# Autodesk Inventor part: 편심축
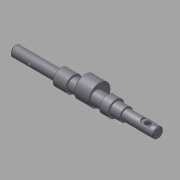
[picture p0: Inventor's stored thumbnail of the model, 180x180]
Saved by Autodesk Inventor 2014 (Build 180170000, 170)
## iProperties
Company: 한국ATC센터
Created: 2015-12
Part Number: 편심축
Document SubType Name: Modeling
Designer: mdu
Density: 7.86 g/cm^3
Mass: 248.518 g
Surface Area: 94.9944 cm^2
Volume: 31.6181 cm^3
Material: 강철, 연강
Appearance: 강철
Author: mdu
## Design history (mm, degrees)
sketch "스케치1"
  geometry: L1 (-84.5, 0)-(84.5, 0); L2 (-84.5, 0)-(-84.5, 6); L3 (-84.5, 6)-(-30.5, 6); L4 (-30.5, 6)-(-30.5, 9.5); L5 (-30.5, 9.5)-(-15.5, 9.5); L6 (-15.5, 9.5)-(-15.5, 7.5); L7 (-15.5, 7.5)-(46.5, 7.5); L8 (84.5, 6)-(84.5, 0); L9 (34.5, 7.5)-(34.5, 9.5); L10 (34.5, 9.5)-(24.5, 9.5); L11 (24.5, 9.5)-(24.5, 7.5); L12 (46.5, 7.5)-(46.5, 6); L13 (46.5, 6)-(84.5, 6); 2 further points
  constraints: 26 end point, 6 parallel, 6 perpendicular, 2 point on line, 1 coincident, 1 horizontal, 1 midpoint
  dimensions: "d1" = 12 diameter of L3 L1; "d2" = 15 diameter of L7 L1; "d4" = 15 distance of L4.end L5.end; "d5" = 19 diameter of L5 L1; "d24" = 10 distance of L9.end L10.end; "d25" = 19 diameter of L10 L1; "d27" = 40 distance between parallel lines of L11 L6; "d28" = 54 distance of L2.end L3.end; "d29" = 50 distance between parallel lines of L8 L9; "d41" = 38 distance between parallel lines of L8 L12; "d42" = 12 diameter of L13 L1
revolve "회전1" stored, may be unused: angle "d6" = 90 deg
node "작업 평면1"
sketch "스케치2"
  geometry: C1 r 7.5 at (0, 0) reference; C2 r 12.5 at (0, 4.5); 1 further point
  constraints: 1 centre point, 1 vertical alignment
  dimensions: "d8" = 4.5 distance of point (0, 0) C2.centre; "d9" = 25 diameter of C2
extrude "돌출1" join sketch "스케치2" distance "d10" = 18; taper "d11" = 0 deg
chamfer "모따기1" distance "d12" = 1; stored, may be unused: second distance "d13" = 2, angle "d14" = 45 deg
chamfer "모따기2" distance "d15" = 0.5; stored, may be unused: second distance "d16" = 2, angle "d17" = 45 deg
node "작업 평면2"
sketch "스케치3"
  geometry: L1 (4, -2)-(18, -2); L2 (18, 2)-(4, 2); L3 (27, 5)-(27, -5) reference; A1 r 2 centre (18, 0) between (18, -2) and (18, 2); A2 r 2 centre (4, 0) between (4, 2) and (4, -2); 2 further points
  constraints: 4 end point, 4 point on circle, 4 tangent, 2 centre point, 1 horizontal, 1 horizontal alignment, 1 midpoint, 1 parallel
  dimensions: "d18" = 7 distance edge to line of A1 L3; "d19" = 4 distance between parallel lines of L2 L1; "d20" = 18 dimension on A1 A2
extrude "돌출2" cut sketch "스케치3" distance "d21" = 2.5; taper "d22" = 0 deg
revolve "회전2" stored, may be unused: angle "d26" = 90 deg
node "작업 평면3"
sketch "스케치4"
  geometry: L1 (44, 5)-(44, -5) reference; 2 further points
  constraints: 1 horizontal alignment
  dimensions: "d30" = 12 distance from line of point (32, 0) L1
hole "구멍1" sketch "스케치4" at (32, 0) diameter "d31" = 6; stored, may be unused: countersink angle "d35" = 90 deg, drill point angle "d37" = 118 deg; dims "d32" = 6, "d33" = 14, "d34" = 3, "d36" = 8
node "작업 평면4"
sketch "스케치5"
  geometry: C1 r 3 at (32, 0) reference; C2 r 8 at (32, 0); 2 further points
  constraints: 1 centre point, 1 coincident, 1 other
  dimensions: "d38" = 16 diameter of C2
extrude "돌출3" cut sketch "스케치5" distance "d39" = 3; taper "d40" = 0 deg
sketch "스케치6"
  geometry: L1 (-83.5, -6)-(-30.5, -6) reference; L2 (-84.5, -5)-(-84.5, 5) reference; L3 (-83.5, 6)-(-30.5, 6) reference; L4 (-62.5, 6)-(-62.5, -6); L5 (-62.5, -6)-(-61, -6); L6 (-62.5, -4.5)-(-61, -6); L7 (-62.5, -6)-(-62.5, -4.5); 2 further points
  constraints: 8 end point, 4 point on line, 2 perpendicular, 1 coincident
  dimensions: "d43" = 22 distance between parallel lines of L4 L2; "d44" = 45 deg angle of L6 L7; "d45" = 3 diameter of L5.end L4
revolve "회전3" stored, may be unused: angle "d46" = 90 deg
node "작업점1"
chamfer "모따기3" distance "d47" = 0.5; stored, may be unused: second distance "d48" = 2, angle "d49" = 45 deg
node "솔리드1"
node "투영된 루프1"
other parameters: "d7" = 8.5
